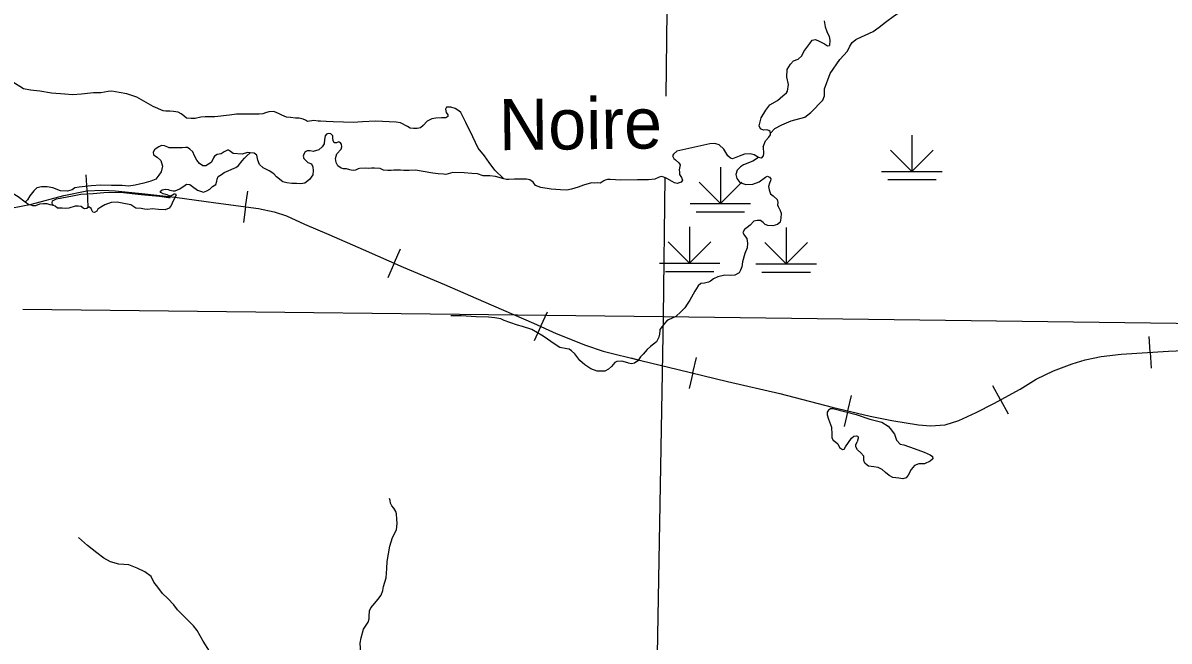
# Model space of a CAD drawing. Extents: x 8749 to 11879, y 13275 to 15339.
# Drawn here: x 10428.7 to 10618.3, y 14235.9 to 14338.3 of the extents above; entities that cross this region are included whole.
import ezdxf

# ---------------------------------------------------------------- set-up
doc = ezdxf.new("R2010")
doc.units = 0
for name, color, linetype in [('Level 31', 7, 'Continuous'), ('Level 35', 7, 'Continuous'), ('Level 40', 7, 'Continuous'), ('Level 44', 7, 'Continuous'), ('Level 5', 7, 'Continuous')]:
    doc.layers.add(name, color=color, linetype=linetype)

msp = doc.modelspace()

# ---------------------------------------------------------------- linework, layer by layer
at = {"layer": 'Level 31'}
for points in [[(10398.97, 14310.23), (10414.23, 14308.52), (10421.12, 14307.75), (10424.5, 14307.53), (10426.71, 14307.62), (10430.13, 14308.25), (10435.49, 14309.69), (10439.27, 14310.46), (10441.84, 14310.59), (10443.98, 14310.46), (10448.35, 14310.05), (10453.85, 14309.42), (10460.6, 14308.47), (10467.67, 14307.53), (10470.24, 14306.99), (10472.31, 14306.31), (10475.28, 14304.96), (10479.32, 14303.22)], [(10479.32, 14303.22), (10485, 14300.74), (10491.62, 14297.81), (10498.46, 14294.97), (10504.9, 14292.13), (10513.19, 14288.57), (10516.93, 14286.86), (10521.79, 14284.92), (10524.7, 14283.93)], [(10524.7, 14283.93), (10530.92, 14282.4), (10537.13, 14280.91), (10545.28, 14278.92), (10553.93, 14276.9), (10562.58, 14274.64), (10568.86, 14273.15)], [(10568.86, 14273.15), (10572.46, 14272.48), (10576.88, 14271.76), (10578.86, 14271.58), (10581.25, 14271.76), (10583.54, 14272.48), (10586.43, 14273.79), (10589.31, 14275.27), (10593.68, 14277.66), (10596.32, 14279.29), (10599.21, 14280.68), (10602.27, 14281.81), (10604.43, 14282.49), (10607.09, 14283.03), (10610.42, 14283.43), (10618.21, 14283.93), (10625.72, 14284.28)]]:
    msp.add_lwpolyline(points, dxfattribs=at)
at = {"layer": 'Level 35'}
for points in [[(10566.73, 14335.61), (10569.39, 14336.85), (10570.37, 14337.55), (10571.42, 14338.38), (10572.88, 14339.46), (10574.11, 14340.26)], [(10561.24, 14338.58), (10561.42, 14337.6), (10561.7, 14336.82), (10562.06, 14335.99), (10562.18, 14335.39)], [(10552.4, 14320.01), (10553.11, 14320.77), (10554.26, 14321.37), (10555.79, 14322.05), (10558.07, 14322.68), (10559.03, 14323.43), (10561.01, 14325.49), (10561.34, 14326.17), (10561.31, 14327.32), (10562.24, 14329.88), (10563.84, 14332.19), (10565.12, 14333.6), (10565.53, 14334.38), (10565.88, 14335.03), (10566.48, 14335.51), (10566.73, 14335.61)], [(10555.19, 14326.98), (10555.34, 14328.09), (10555.06, 14329.27), (10555.11, 14330.55), (10555.69, 14331.45), (10556.19, 14332), (10556.97, 14332.23), (10557.57, 14332.83), (10557.9, 14333.51), (10558.88, 14334.84), (10559.3, 14335.4), (10559.81, 14335.52), (10560.41, 14335.22), (10561.31, 14334.77), (10561.81, 14334.47), (10562.13, 14334.49)], [(10562.18, 14335.39), (10562.13, 14334.49)], [(10444.61, 14326.76), (10443.39, 14326.98), (10442.78, 14326.91), (10441.57, 14326.71), (10440.37, 14326.66), (10438.4, 14326.44), (10436.91, 14326.34), (10435.65, 14326.44), (10433.42, 14326.64), (10431.48, 14326.95), (10429.95, 14327.15), (10428.82, 14327.37), (10428.21, 14327.72), (10426.73, 14328.63), (10424.33, 14329.96), (10424.01, 14330.15)], [(10458.14, 14322.68), (10457.19, 14322.41), (10456.52, 14322.41), (10455.74, 14322.5), (10455.3, 14322.85), (10454.9, 14323.22), (10454.39, 14323.46), (10453.62, 14323.59), (10452.99, 14323.66), (10452.37, 14323.66), (10451.93, 14323.71), (10450.23, 14324.4), (10448.69, 14325.31), (10447.53, 14325.95), (10445.89, 14326.54), (10444.61, 14326.76)], [(10551.14, 14317.76), (10551.55, 14318.73), (10552.13, 14319.36), (10552.38, 14319.76), (10552.4, 14320.01), (10552.35, 14320.26), (10552.13, 14320.47), (10551.75, 14320.54), (10551.3, 14320.49), (10550.92, 14320.59), (10550.72, 14320.74), (10550.52, 14321.24), (10550.85, 14322.57), (10551.58, 14323.81), (10552.25, 14324.71), (10553.56, 14325.41), (10554.44, 14326.19), (10555.01, 14326.69), (10555.19, 14326.98)], [(10508.25, 14312.45), (10506.75, 14313.86), (10505.84, 14315.17), (10505.06, 14316.27), (10504.03, 14317.53), (10503.12, 14319.4), (10501.99, 14321.78), (10501.15, 14323.41), (10500.83, 14323.69), (10500.22, 14324.08), (10499.48, 14324.31), (10499.16, 14324.33), (10498.79, 14324.31), (10498.6, 14323.96), (10498.72, 14323.45), (10498.99, 14323.05), (10498.99, 14322.76), (10498.65, 14322.54), (10497.93, 14322.54), (10497.02, 14322.51), (10496.36, 14322.36), (10495.6, 14321.99), (10494.94, 14321.28), (10494.47, 14320.91), (10493.93, 14320.77), (10493.34, 14320.77), (10492.77, 14320.84), (10492.31, 14321.13), (10491.15, 14321.72), (10490.46, 14321.85)], [(10476.83, 14322.12), (10475.76, 14321.95), (10475.46, 14322.14), (10475.05, 14322.31), (10474.43, 14322.49), (10473.77, 14322.51), (10472.98, 14322.61), (10472.32, 14322.68), (10471.51, 14323), (10470.97, 14323.27), (10470.21, 14323.57), (10469.4, 14323.54), (10468.81, 14323.37), (10468.39, 14323.2), (10467.8, 14323.15), (10467.06, 14323.15), (10466.18, 14323.15), (10465.19, 14323.15), (10464.02, 14323.15), (10462.86, 14323), (10460.43, 14322.73), (10459.72, 14322.73), (10458.83, 14322.73), (10458.14, 14322.68)], [(10490.46, 14321.85), (10487.03, 14321.97), (10484.89, 14321.9), (10483.32, 14321.8), (10481.75, 14321.85), (10480.05, 14321.87), (10478.87, 14321.92), (10477.96, 14321.97), (10477.57, 14321.99), (10476.83, 14322.12)], [(10485.32, 14314.23), (10484.4, 14314.18), (10484.17, 14314.13), (10483.72, 14313.9), (10483.37, 14313.85), (10482.99, 14313.9), (10482.79, 14313.95), (10482.26, 14314.1), (10481.76, 14314.1), (10481.36, 14314.23), (10480.78, 14314.58), (10480.51, 14315.18), (10480.43, 14315.84), (10480.66, 14316.61), (10481.36, 14317.34), (10481.44, 14317.74), (10481.41, 14318.2), (10481.16, 14318.47), (10480.98, 14318.55), (10480.58, 14318.42), (10480.18, 14318.42), (10480.01, 14318.82), (10480, 14319.2), (10479.98, 14319.58), (10479.63, 14319.9), (10479.28, 14319.98), (10478.93, 14319.85), (10478.68, 14319.55), (10478.6, 14318.95), (10478.55, 14318.27), (10478.2, 14317.74), (10477.65, 14317.24), (10476.72, 14316.99)], [(10457.1, 14316.24), (10456.81, 14316.94), (10456.34, 14317.37), (10455.91, 14317.62), (10455.58, 14317.64), (10455.03, 14317.59), (10454.33, 14317.57), (10453.58, 14317.57), (10452.87, 14317.59), (10452.7, 14317.67), (10452.1, 14317.92), (10451.62, 14317.95), (10451.19, 14317.77), (10450.77, 14317.49), (10450.47, 14317.27), (10450.24, 14316.89), (10450.29, 14316.44), (10450.92, 14316.01), (10451.54, 14315.46)], [(10551.14, 14317.76), (10551.21, 14316.66), (10551.14, 14316.23), (10550.84, 14315.88), (10550.39, 14315.96), (10549.66, 14316.41), (10549.03, 14316.61), (10548.1, 14316.53), (10547.17, 14316.21), (10546.07, 14315.76), (10545.74, 14315.88), (10545.34, 14316.26), (10544.64, 14317.36), (10543.89, 14318.09), (10543.19, 14318.32), (10542.33, 14318.27), (10540.83, 14317.92), (10536.89, 14317.01), (10536.31, 14316.56), (10536.16, 14316.26), (10536.36, 14315.81), (10536.68, 14315.58)], [(10453.06, 14309.56), (10452.58, 14309.78), (10451.93, 14309.96), (10451.53, 14310.21), (10451.43, 14310.36), (10451.75, 14310.64), (10452.28, 14310.74), (10452.73, 14310.71), (10453.03, 14310.56), (10453.56, 14310.49), (10453.91, 14310.49), (10454.64, 14310.81), (10455.52, 14311.39), (10455.79, 14311.59), (10456.32, 14311.54), (10456.75, 14311.16), (10457.57, 14310.56), (10458.6, 14310.26), (10459.13, 14310.49), (10459.61, 14310.74), (10460.08, 14311.16), (10460.6, 14311.49), (10460.76, 14312.07), (10460.81, 14312.42), (10461.01, 14312.85), (10461.56, 14313.17), (10461.98, 14313.48), (10462.79, 14313.83), (10463.67, 14314.23), (10463.92, 14314.33), (10464.39, 14314.66), (10464.97, 14315.43), (10465.37, 14315.86), (10465.75, 14316.24), (10466.29, 14316.77)], [(10471.7, 14311.97), (10470.65, 14312.77), (10470.2, 14313.3), (10469.42, 14313.75), (10468.47, 14314.28), (10467.82, 14314.83), (10467.59, 14315.56), (10467.42, 14316.36), (10466.97, 14316.71), (10466.29, 14316.77), (10465.86, 14316.82), (10464.98, 14316.51), (10463.48, 14316.64), (10463.05, 14316.99), (10462.73, 14317.22), (10462.52, 14317.22), (10462, 14316.94), (10461.5, 14316.59), (10460.84, 14316.46), (10460.39, 14316.21), (10460.24, 14315.94), (10460.12, 14315.63), (10459.84, 14315.16), (10458.99, 14314.58), (10458.46, 14314.58), (10457.93, 14314.98), (10457.46, 14315.53), (10457.1, 14316.24)], [(10476.72, 14316.99), (10476.22, 14317.09), (10476.02, 14317.09), (10475.72, 14317.07), (10475.39, 14316.92), (10475.16, 14316.54), (10475.09, 14316.21), (10475.16, 14315.79), (10475.84, 14315.18), (10476.44, 14314.91), (10476.67, 14314.43), (10476.72, 14313.75), (10476.67, 14313.1), (10476.09, 14312.35), (10475.32, 14311.74), (10474.66, 14311.62), (10473.94, 14311.67), (10473.18, 14311.67), (10472.35, 14311.77), (10471.7, 14311.97)], [(10429.1, 14308.6), (10427.89, 14309.46), (10427.07, 14309.98), (10425.86, 14310.59), (10424.11, 14311.21), (10421.67, 14311.92), (10418.46, 14312.7), (10414.27, 14313.7), (10409.75, 14314.91)], [(10451.54, 14315.46), (10451.8, 14314.53), (10451.59, 14313.63), (10451.19, 14313.05), (10450.69, 14312.4), (10449.84, 14312.07), (10448.68, 14311.72), (10447.25, 14311.39), (10446.25, 14311.24), (10445.12, 14311.32), (10443.37, 14311.37), (10441.58, 14311.42), (10439.98, 14311.27), (10438.02, 14311.09), (10437.29, 14310.94), (10436.84, 14310.64), (10436.06, 14310.41), (10434.94, 14310.49), (10433.63, 14310.96)], [(10508.25, 14312.45), (10506.87, 14312.82), (10505.92, 14312.95), (10504.87, 14312.97), (10503.91, 14313.3), (10502.96, 14313.35), (10501.71, 14313.42), (10499.85, 14313.48), (10498.64, 14313.15), (10498.27, 14313.22), (10497.42, 14313.27), (10496.51, 14313.4), (10493.65, 14313.88), (10492.6, 14313.85), (10491.74, 14313.85), (10491.19, 14313.88), (10490.06, 14313.9), (10489.64, 14313.85), (10489.06, 14313.83), (10488.36, 14313.88), (10487.81, 14314.15), (10486.88, 14314.2), (10486.35, 14314.2), (10485.85, 14314.15), (10485.32, 14314.23)], [(10536.68, 14315.58), (10537.2, 14315.12), (10537.41, 14314.79), (10537.37, 14314.49), (10537.27, 14313.96), (10537.3, 14313.54), (10537.34, 14313.15), (10537.63, 14312.68), (10537.8, 14312.24), (10537.58, 14311.88), (10536.94, 14311.7), (10536.48, 14311.79), (10536.12, 14312)], [(10550.39, 14315.96), (10549.43, 14315.36), (10547.9, 14314.76), (10547.4, 14314.41), (10546.87, 14313.91), (10546.67, 14313.18), (10546.82, 14312.48), (10547.28, 14311.82), (10548.28, 14311.5), (10549.48, 14311.55), (10550.51, 14311.95), (10551.54, 14312.7), (10551.89, 14312.88), (10552.24, 14312.75), (10552.42, 14312.45), (10552.39, 14312.12), (10552.22, 14311.72), (10552.07, 14311.19), (10552.14, 14310.62), (10552.39, 14309.96), (10552.8, 14309.66), (10553.47, 14309.04), (10553.6, 14308.56), (10553.52, 14308.13), (10553.65, 14307.88), (10553.97, 14307.2), (10554.12, 14306.77), (10554.12, 14306.72), (10554.1, 14305.92), (10554, 14305.29), (10553.52, 14304.87), (10552.74, 14304.67), (10551.92, 14304.72)], [(10513.51, 14311.37), (10513.14, 14311.89), (10512.59, 14312.27), (10511.99, 14312.42), (10511.21, 14312.42), (10510, 14312.42), (10509.07, 14312.35), (10508.7, 14312.35), (10508.25, 14312.45)], [(10536.12, 14312), (10535.24, 14312.51), (10534.75, 14312.75), (10534.34, 14312.81), (10533.96, 14312.72), (10533.27, 14312.41), (10532.19, 14312.29), (10530.35, 14312.28), (10527.61, 14312.24), (10525.87, 14312.33), (10525.42, 14312.35), (10525.04, 14312.23), (10524.82, 14312.12), (10524.48, 14311.88), (10524.18, 14311.75), (10523.78, 14311.77), (10523.29, 14311.75), (10522.78, 14311.77)], [(10433.63, 14310.96), (10432.71, 14311.14), (10431.76, 14311.11), (10430.98, 14310.94), (10430.5, 14310.46), (10429.87, 14309.61), (10429.45, 14309), (10429.1, 14308.6)], [(10522.78, 14311.77), (10521.44, 14311.39), (10520.54, 14311.09), (10519.46, 14310.74), (10518.68, 14310.59), (10517.65, 14310.64), (10516.12, 14310.74), (10514.37, 14310.99), (10513.51, 14311.37)], [(10433.76, 14308.05), (10433.23, 14308.13), (10432.73, 14308.3), (10432.13, 14308.3), (10431.42, 14308.28), (10430.77, 14308), (10430.32, 14308), (10430.07, 14308.08), (10429.69, 14308.13), (10429.1, 14308.6)], [(10453.06, 14309.56), (10453.7, 14309.96), (10453.93, 14309.96), (10454.06, 14309.76), (10453.58, 14308.8), (10453.23, 14308.05), (10452.9, 14307.62), (10452.22, 14307.3), (10451.12, 14307.35), (10450.07, 14307.5), (10449.36, 14307.4), (10448.81, 14307.45), (10448.26, 14307.52), (10447.38, 14307.62), (10446.53, 14308.13), (10445.12, 14308.43), (10444.27, 14308.58), (10443.29, 14308.55), (10442.24, 14308.15), (10441.59, 14307.77), (10441.11, 14307.42), (10440.91, 14307.12), (10440.56, 14306.87), (10440.28, 14306.95), (10440.13, 14307.25), (10439.98, 14307.55), (10439.58, 14307.82), (10439.25, 14307.55), (10438.88, 14307.47), (10438.65, 14307.57), (10438.32, 14307.87), (10437.82, 14307.95), (10437.35, 14307.9), (10436.29, 14307.62), (10435.82, 14307.55), (10435.21, 14307.57), (10434.44, 14307.62), (10434.06, 14307.9), (10433.76, 14308.05), (10433.58, 14308.28), (10433.53, 14308.5), (10433.61, 14308.83), (10434.23, 14309.13), (10436.92, 14309.63), (10438.3, 14309.93), (10440.31, 14310.03), (10442.09, 14310.21), (10444.82, 14310.26), (10448.29, 14309.88), (10451.3, 14309.58), (10452.78, 14309.36), (10453.04, 14309.38), (10453.06, 14309.56)], [(10551.92, 14304.72), (10551.49, 14304.89), (10551.17, 14305.25), (10550.72, 14305.55), (10550.16, 14305.57), (10549.61, 14305.42), (10549.03, 14304.79), (10548.51, 14304.37), (10548.08, 14304.07), (10547.8, 14303.59), (10548.06, 14303.06), (10548.48, 14302.58), (10548.58, 14301.8), (10548.51, 14301.05), (10548.11, 14300.1), (10547.73, 14298.72)], [(10547.73, 14298.72), (10547.64, 14297.9), (10547.44, 14297.35), (10547.19, 14296.9), (10546.49, 14296.52), (10545.79, 14296.47), (10544.83, 14296.5), (10543.65, 14296.22), (10542.95, 14295.92), (10542.48, 14295.52), (10542.1, 14295.34), (10541.47, 14295.16), (10540.87, 14295.11), (10540.42, 14294.76), (10539.87, 14293.86), (10539.04, 14292.35), (10538.59, 14291.7), (10538.18, 14291.1), (10537.56, 14290.42), (10536.73, 14289.69), (10535.48, 14289.09), (10535.22, 14288.94), (10534.82, 14288.53)], [(10512.92, 14287.52), (10511.35, 14287.99), (10510.55, 14288.24), (10509.24, 14288.7), (10508.31, 14289.02), (10507.76, 14289.3), (10506.78, 14289.47), (10505.71, 14289.55), (10503.7, 14289.6), (10501.21, 14289.75), (10499.51, 14289.78)], [(10534.82, 14288.53), (10534.05, 14287.54), (10534.05, 14287.34), (10534, 14286.76), (10533.92, 14286.23), (10533.52, 14285.46), (10532.54, 14284.68), (10531.99, 14284.23), (10531.62, 14283.82), (10531.34, 14283.42), (10530.89, 14282.99), (10530.44, 14282.34), (10529.86, 14281.94), (10529.41, 14281.86), (10528.88, 14281.94), (10528.76, 14281.98)], [(10528.76, 14281.98), (10527.78, 14282.27), (10526.95, 14282.22), (10526.65, 14282.07), (10526.05, 14281.41), (10525.59, 14280.96), (10524.99, 14280.63), (10524.67, 14280.61), (10523.69, 14280.61), (10522.66, 14281.01), (10521.66, 14281.69), (10520.85, 14282.39), (10520, 14283.47), (10519.47, 14283.97), (10519.05, 14284.25), (10518.69, 14284.33), (10517.52, 14284.55), (10516.76, 14285.05), (10514.76, 14286.39), (10512.92, 14287.52)], [(10562.91, 14274.4), (10562.28, 14274.4), (10561.95, 14274.14), (10561.77, 14273.84), (10561.75, 14273.41), (10562, 14272.68), (10562.45, 14271.36), (10562.53, 14270.12), (10562.53, 14269.59), (10562.73, 14269.21), (10563.21, 14268.88), (10563.51, 14268.61), (10563.77, 14268), (10564.27, 14267.64), (10564.55, 14267.72), (10564.8, 14268.07), (10565.28, 14268.81), (10565.76, 14269.54), (10566.14, 14269.84), (10566.6, 14269.89), (10566.8, 14269.87), (10566.9, 14269.77), (10566.87, 14269.54), (10566.71, 14268.92)], [(10562.91, 14274.4), (10566.57, 14273.43), (10568.79, 14272.7), (10570.79, 14272.17), (10571.82, 14271.51), (10572.15, 14271.11), (10572.88, 14270.17), (10573.24, 14269.21), (10573.82, 14268.56), (10574.43, 14268.4), (10576.12, 14267.82), (10577.78, 14267.24), (10578.32, 14267.01), (10578.82, 14266.79), (10579.17, 14266.51), (10579.22, 14266.12)], [(10579.22, 14266.12), (10578.8, 14265.75), (10577.86, 14265.29), (10576.93, 14265.27), (10576.22, 14264.99), (10575.66, 14264.36), (10575.18, 14263.42), (10574.85, 14262.99), (10574.25, 14262.82), (10573.59, 14262.92), (10572.63, 14263.02), (10572.03, 14263.35), (10571.42, 14263.83), (10570.84, 14264.33), (10570.21, 14264.69), (10569.5, 14264.81), (10568.57, 14264.89), (10568.36, 14265.04), (10567.96, 14265.42), (10567.83, 14265.85), (10567.81, 14266.53), (10567.33, 14267.11), (10566.75, 14267.59), (10566.52, 14268.07), (10566.52, 14268.43), (10566.71, 14268.92)], [(10490.52, 14254.34), (10490.61, 14255.4), (10490.56, 14256.13), (10490.48, 14256.99), (10490.41, 14257.42), (10490.08, 14257.92), (10489.73, 14258.35), (10489.5, 14258.76), (10489.47, 14259.19), (10489.37, 14259.54)], [(10486.04, 14240.95), (10486.27, 14241.45), (10486.93, 14242.23), (10487.43, 14242.81), (10487.99, 14243.55), (10488.22, 14244.33), (10488.37, 14244.99), (10488.82, 14246.4), (10488.9, 14247.94), (10488.95, 14249.11), (10489.4, 14251.66), (10489.86, 14253.08), (10490.52, 14254.34)], [(10453.68, 14241.95), (10452.68, 14242.99), (10451.79, 14243.83), (10451.01, 14244.87), (10450.38, 14245.72), (10449.9, 14246.64), (10448.86, 14247.39), (10447.6, 14248.03), (10446.24, 14248.58), (10444.57, 14248.66), (10443.18, 14249.06), (10442.07, 14249.67), (10440.91, 14250.55), (10439.37, 14251.74), (10437.88, 14253.08)], [(10462.27, 14229), (10461.13, 14230.6), (10460.6, 14231.48), (10460.12, 14232.75), (10459.57, 14234.26), (10458.51, 14235.91), (10457.52, 14237.68), (10456.92, 14238.46), (10456.21, 14239.19), (10455.33, 14240.05), (10454.29, 14241.14), (10453.68, 14241.95)], [(10484.38, 14229.34), (10484.55, 14230.99), (10484.61, 14232.13), (10484.63, 14233.29), (10484.55, 14234.76), (10484.5, 14235.62), (10484.68, 14236.5), (10485.06, 14237.92), (10485.82, 14239.08), (10485.97, 14239.61), (10485.97, 14240.04), (10486.04, 14240.95)]]:
    msp.add_lwpolyline(points, dxfattribs=at)
at = {"layer": 'Level 40'}
for p, q in [((10439.32, 14310.46), (10439.18, 14313.1)), ((10439.32, 14310.46), (10439.46, 14307.82)), ((10465.54, 14307.81), (10465.89, 14310.43)), ((10465.54, 14307.81), (10465.19, 14305.2)), ((10490.11, 14298.48), (10491.18, 14300.89)), ((10490.11, 14298.48), (10489.05, 14296.06)), ((10514.36, 14288.04), (10515.46, 14290.44)), ((10514.36, 14288.04), (10513.26, 14285.64)), ((10615.2, 14283.74), (10615.03, 14286.37)), ((10539.53, 14280.32), (10540.16, 14282.89)), ((10615.2, 14283.74), (10615.36, 14281.1)), ((10539.53, 14280.32), (10538.91, 14277.76)), ((10590.42, 14275.88), (10589.16, 14278.2)), ((10565.17, 14274.03), (10565.78, 14276.6)), ((10590.42, 14275.88), (10591.69, 14273.57)), ((10565.17, 14274.03), (10564.56, 14271.46))]:
    msp.add_line(p, q, dxfattribs=at)
for points in [[(10426.71, 14307.62), (10430.13, 14308.25), (10435.49, 14309.69), (10439.27, 14310.46), (10441.84, 14310.59), (10443.98, 14310.46), (10448.35, 14310.05), (10453.85, 14309.42), (10460.6, 14308.47), (10467.67, 14307.53), (10470.24, 14306.99), (10472.31, 14306.31), (10475.28, 14304.96), (10479.32, 14303.22), (10485, 14300.74), (10491.62, 14297.81), (10498.46, 14294.97), (10504.9, 14292.13), (10513.19, 14288.57), (10516.93, 14286.86), (10521.79, 14284.92), (10524.7, 14283.93), (10530.92, 14282.4), (10537.13, 14280.91), (10545.28, 14278.92), (10553.93, 14276.9), (10562.58, 14274.64), (10568.86, 14273.15), (10572.46, 14272.48), (10576.88, 14271.76), (10578.86, 14271.58), (10581.25, 14271.76), (10583.54, 14272.48), (10586.43, 14273.79), (10589.31, 14275.27), (10593.68, 14277.66), (10596.32, 14279.29), (10599.21, 14280.68), (10602.27, 14281.81), (10604.43, 14282.49), (10607.09, 14283.03), (10610.42, 14283.43), (10618.21, 14283.93), (10625.72, 14284.28)], [(10529.27, 14282.8), (10530.92, 14282.4)]]:
    msp.add_lwpolyline(points, dxfattribs=at)
at = {"layer": 'Level 44'}
for p, q in [((10575.77, 14319.68), (10575.77, 14313.68)), ((10575.77, 14313.68), (10572.23, 14317.22)), ((10575.77, 14313.68), (10579.3, 14317.22)), ((10544.09, 14314.36), (10544.09, 14308.36)), ((10570.77, 14313.68), (10580.77, 14313.68)), ((10571.77, 14312.32), (10579.77, 14312.32)), ((10544.09, 14308.36), (10540.56, 14311.9)), ((10544.09, 14308.36), (10547.63, 14311.9)), ((10539.09, 14308.36), (10549.09, 14308.36)), ((10540.09, 14307), (10548.09, 14307)), ((10538.99, 14304.5), (10538.99, 14298.5)), ((10554.97, 14304.38), (10554.97, 14298.38)), ((10538.99, 14298.5), (10535.45, 14302.04)), ((10538.99, 14298.5), (10542.52, 14302.04)), ((10554.97, 14298.38), (10551.43, 14301.91)), ((10554.97, 14298.38), (10558.51, 14301.91)), ((10533.99, 14298.5), (10543.99, 14298.5)), ((10534.99, 14297.14), (10542.99, 14297.14)), ((10549.97, 14298.38), (10559.97, 14298.38)), ((10550.97, 14297.02), (10558.97, 14297.02))]:
    msp.add_line(p, q, dxfattribs=at)
at = {"layer": 'Level 5'}
for points in [[(10535.42, 14354.34), (10535.06, 14326.12)], [(10534.9, 14312.7), (10534.61, 14289.64)], [(10428.7, 14290.86), (10534.61, 14289.64)], [(10534.61, 14289.64), (10532.75, 14184.09)], [(10534.61, 14289.64), (10640.71, 14288.3)]]:
    msp.add_lwpolyline(points, dxfattribs=at)

# ---------------------------------------------------------------- texts
at = {"layer": 'Level 35'}
msp.add_text('Noire', height=8.448, rotation=0.6592, dxfattribs=at).set_placement((10507.48, 14317.18))

doc.saveas('drawing.dxf')
